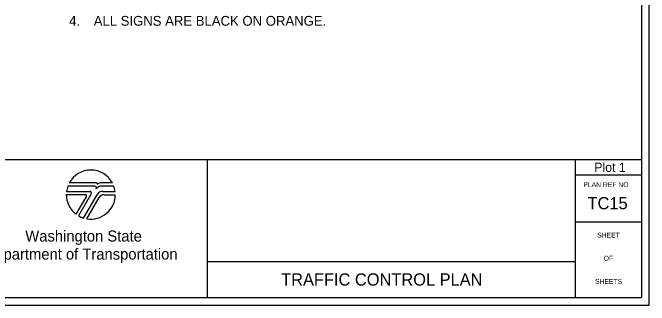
# Model space of a CAD drawing. Extents: x 99988 to 100172, y 99995 to 100047.
# Drawn here: x 100010.62 to 100015.81, y 99999.94 to 100002.32 of the extents above; entities that cross this region are included whole.
import ezdxf

# ---------------------------------------------------------------- set-up
doc = ezdxf.new("R2010")
doc.units = 0
for name, color, linetype in [('Level 20', 7, 'Continuous'), ('SH_GI_PlotLimits', 7, 'Continuous'), ('SH_GI_SheetBorder', 7, 'Continuous'), ('SH_GI_SheetLocationText', 7, 'Continuous'), ('SH_GI_SheetTextInCells', 7, 'Continuous'), ('SH_GI_TitleBlockText', 7, 'Continuous'), ('SH_GI_WSDOTLogo', 7, 'Continuous')]:
    doc.layers.add(name, color=color, linetype=linetype)

msp = doc.modelspace()

# ---------------------------------------------------------------- linework, layer by layer
at = {"layer": 'SH_GI_PlotLimits'}
msp.add_lwpolyline([(99999.3125, 99999.9375), (100015.8125, 99999.9375), (100015.8125, 100010.4375), (99999.3125, 100010.4375)], close=True, dxfattribs=at)
at = {"layer": 'SH_GI_SheetBorder'}
for p, q in [((100015.75, 100010.375), (100015.75, 100000)), ((100000, 100001.1259), (100015.75, 100001.1259)), ((100012.2055, 100001.1259), (100012.2055, 100000)), ((100015.2079, 100001.1259), (100015.2079, 100000)), ((100015.2079, 100001.0008), (100015.75, 100001.0008)), ((100015.2079, 100000.6176), (100015.75, 100000.6176)), ((100012.2055, 100000.2955), (100015.2079, 100000.2955)), ((100000, 100000), (100015.75, 100000))]:
    msp.add_line(p, q, dxfattribs=at)
at = {"layer": 'SH_GI_WSDOTLogo'}
for p, q in [((100011.303, 100000.9354), (100011.0815, 100000.9354)), ((100011.433, 100000.9354), (100011.3351, 100000.9354)), ((100011.2894, 100000.9094), (100011.0697, 100000.9094)), ((100011.343, 100000.9094), (100011.3429, 100000.9094)), ((100011.4448, 100000.9094), (100011.343, 100000.9094)), ((100011.0572, 100000.84), (100011.2148, 100000.84)), ((100011.059, 100000.8661), (100011.2496, 100000.8661)), ((100011.222, 100000.8277), (100011.1364, 100000.6807)), ((100011.261, 100000.8464), (100011.1567, 100000.6672)), ((100011.1989, 100000.6487), (100011.3089, 100000.839)), ((100011.3558, 100000.8661), (100011.4555, 100000.8661)), ((100011.3655, 100000.8394), (100011.4572, 100000.8394)), ((100011.2244, 100000.6428), (100011.3242, 100000.8156))]:
    msp.add_line(p, q, dxfattribs=at)
for centre, radius, start, end in [((100011.2572, 100000.84), 0.2, 28.4787, 151.532), ((100011.303, 100000.9263), 0.00903, 329.8742, 90.0033), ((100011.3352, 100000.9066), 0.0287, 90.0072, 148.1676), ((100011.2572, 100000.84), 0.2, 159.696, 172.5057), ((100011.2894, 100000.8946), 0.0148, 327.8418, 89.9985), ((100011.3429, 100000.861), 0.0484, 89.9953, 147.8238), ((100011.2572, 100000.84), 0.2, 7.4943, 20.2941), ((100011.2572, 100000.84), 0.2, 179.9986, 232.8433), ((100011.2149, 100000.8318), 0.0082, 329.7436, 90), ((100011.2572, 100000.84), 0.2, 260.5455, 359.8086), ((100011.2497, 100000.853), 0.0131, 329.7683, 90), ((100011.3558, 100000.8119), 0.0542, 90, 149.9974), ((100011.3654, 100000.7918), 0.0476, 90, 150.0543), ((100011.2572, 100000.84), 0.2, 239.7929, 253.0448)]:
    msp.add_arc(centre, radius, start, end, dxfattribs=at)

# ---------------------------------------------------------------- texts
at = {"layer": 'Level 20'}
for s, p in [('4.', (100011.081, 100002.2169)), ('ALL SIGNS ARE BLACK ON ORANGE.', (100011.281, 100002.2169))]:
    msp.add_text(s, height=0.08, dxfattribs=at).set_placement(p)
at = {"layer": 'SH_GI_SheetBorder'}
msp.add_text('PLAN REF NO', height=0.040032, dxfattribs=at).set_placement((100015.2747, 100000.9008))
at = {"layer": 'SH_GI_SheetLocationText'}
msp.add_text('Plot 1', height=0.075, dxfattribs=at).set_placement((100015.3639, 100001.0252))
at = {"layer": 'SH_GI_SheetTextInCells'}
for s, height, p in [('Washington State', 0.090072, (100010.7229, 100000.4571)), ('SHEET', 0.04003, (100015.3877, 100000.4896)), ('Department of Transportation', 0.090072, (100010.3916, 100000.3101)), ('OF', 0.04003, (100015.4406, 100000.3008)), ('SHEETS', 0.04003, (100015.3698, 100000.112))]:
    msp.add_text(s, height=height, dxfattribs=at).set_placement(p)
at = {"layer": 'SH_GI_TitleBlockText'}
for s, p in [('TC15', (100015.3088, 100000.72)), ('TRAFFIC CONTROL PLAN', (100012.8099, 100000.0977))]:
    msp.add_text(s, height=0.1, dxfattribs=at).set_placement(p)

doc.saveas('drawing.dxf')
